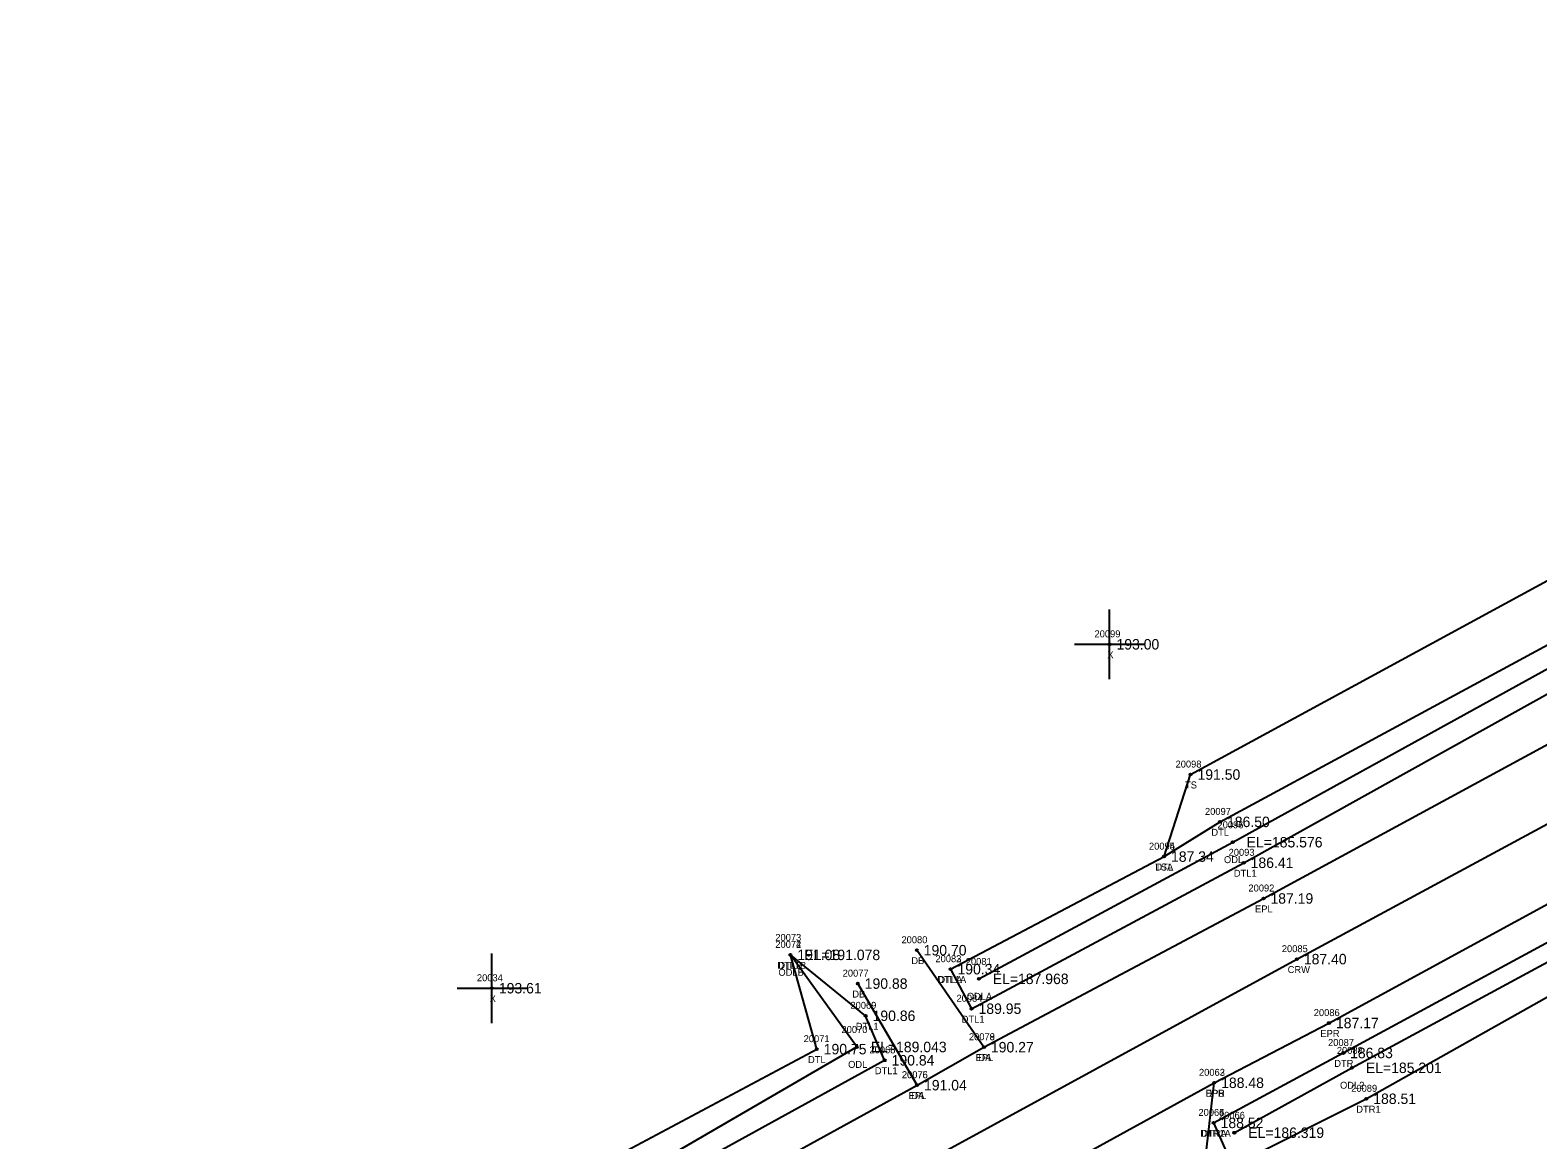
# Model space of a CAD drawing. Extents: x 2279528 to 2280976, y 1061373 to 1062235.
# Drawn here: x 2279546.3 to 2279762.5, y 1061498.9 to 1061658.1 of the extents above; entities that cross this region are included whole.
import ezdxf

# ---------------------------------------------------------------- set-up
doc = ezdxf.new("R2010")
doc.units = 0
for name, color, linetype in [('RD_DTM_BkLn1', 7, 'Continuous'), ('RD_DTM_BkLn2', 7, 'Continuous'), ('RD_DTM_BkLn_txCode', 7, 'Continuous'), ('RD_EX_Driveway', 7, 'Continuous'), ('RD_EX_Driveway_txCode', 7, 'Continuous'), ('RD_EX_H2O', 7, 'Continuous'), ('RD_EX_H2O_txCode', 7, 'Continuous'), ('RD_EX_Misc', 7, 'Continuous'), ('RD_EX_Misc_txCode', 7, 'Continuous'), ('RD_EX_Road', 7, 'Continuous'), ('RD_EX_Road_txCode', 7, 'Continuous'), ('RD_EX_TX_Driveway_ELEV', 7, 'Continuous'), ('RD_EX_TX_H2O_ELEV', 7, 'Continuous'), ('RD_EX_TX_Misc_ELEV', 7, 'Continuous'), ('RD_EX_TX_Road_ELEV', 7, 'Continuous'), ('RD_HC_Survey_ELEV', 7, 'Continuous'), ('RD_HC_Survey_txCode', 7, 'Continuous'), ('RD_SMD_Locator', 7, 'Continuous')]:
    doc.layers.add(name, color=color, linetype=linetype)

msp = doc.modelspace()

# ---------------------------------------------------------------- linework, layer by layer
at = {"layer": 'RD_DTM_BkLn1'}
msp.add_lwpolyline([(2279559.79, 1061433.13), (2279641.23, 1061477.49), (2279727.93, 1061524.84), (2279814.76, 1061571.75), (2279901.26, 1061618.64), (2279982.8, 1061662.56), (2280064.7, 1061706.86), (2280148.08, 1061751.86), (2280234.22, 1061798.46), (2280310.96, 1061840.01), (2280397.69, 1061887.57), (2280487.27, 1061936.5), (2280573.03, 1061983.12), (2280654.64, 1062027.66), (2280741.28, 1062074.45), (2280833.39, 1062123.87), (2280892.52, 1062155.9), (2280939.46, 1062181.85)], dxfattribs=at)
at = {"layer": 'RD_DTM_BkLn2'}
msp.add_lwpolyline([(2279708.88, 1061539.55), (2279712.68, 1061551.32), (2279799.03, 1061598.26), (2279864.37, 1061637.89), (2279890.29, 1061645.53)], dxfattribs=at)
at = {"layer": 'RD_EX_Driveway'}
for p, q in [((2279683.06, 1061512.21), (2279673.42, 1061526.12)), ((2279673.46, 1061506.76), (2279664.96, 1061521.33))]:
    msp.add_line(p, q, dxfattribs=at)
msp.add_lwpolyline([(2279687.22, 1061491.24), (2279694.36, 1061490.16), (2279705.74, 1061483.55), (2279717.08, 1061489.5), (2279714.88, 1061496.65), (2279716.07, 1061507.1)], dxfattribs=at)
at = {"layer": 'RD_EX_H2O'}
for points in [[(2279678.26, 1061523.4), (2279708.88, 1061539.55), (2279716.91, 1061544.53), (2279803.91, 1061591.58), (2279817.92, 1061601.16), (2279890.29, 1061645.53), (2279903.5, 1061647.72), (2279912.54, 1061647.23), (2279918.28, 1061645.97)], [(2279682.32, 1061522.01), (2279718.73, 1061541.61), (2279805.01, 1061589.19), (2279818.85, 1061600.16), (2279890.75, 1061643.58), (2279903.5, 1061647.72)], [(2279678.26, 1061523.4), (2279681.28, 1061517.73), (2279720.3, 1061538.66), (2279806.21, 1061586.46), (2279822.44, 1061595.21), (2279894.25, 1061633.83), (2279918.28, 1061645.97)], [(2279715.99, 1061501.35), (2279734.56, 1061511.38), (2279821.65, 1061558.53), (2279857.43, 1061578.68), (2279860, 1061573.39)], [(2279718.96, 1061499.94), (2279735.82, 1061509.25), (2279822.86, 1061556.33), (2279855.49, 1061575.73)], [(2279715.99, 1061501.35), (2279718.69, 1061495.17), (2279737.88, 1061504.81), (2279824.53, 1061553.58), (2279860, 1061573.39)], [(2279546.29, 1061453.71), (2279630.41, 1061496.6), (2279659.08, 1061511.93), (2279655.3, 1061525.45)], [(2279549.3, 1061448.96), (2279632.68, 1061493.55), (2279664.83, 1061512.24), (2279655.3, 1061525.45)], [(2279552, 1061445.3), (2279634.13, 1061491.29), (2279668.82, 1061510.33), (2279666.09, 1061516.71), (2279655.3, 1061525.45)]]:
    msp.add_lwpolyline(points, dxfattribs=at)
at = {"layer": 'RD_EX_Misc'}
for p, q in [((2279701.06, 1061565), (2279701.06, 1061575)), ((2279696.06, 1061570), (2279706.06, 1061570)), ((2279612.5, 1061515.67), (2279612.5, 1061525.67)), ((2279607.5, 1061520.67), (2279617.5, 1061520.67))]:
    msp.add_line(p, q, dxfattribs=at)
at = {"layer": 'RD_EX_Road'}
for points in [[(2279554.31, 1061441.46), (2279636.61, 1061486.51), (2279673.46, 1061506.76), (2279683.06, 1061512.21), (2279723.14, 1061533.54), (2279809.28, 1061580.29), (2279896.91, 1061627.91), (2279977.07, 1061671.02), (2280059.64, 1061715.57), (2280142.91, 1061760.72), (2280228.83, 1061807.06), (2280306.04, 1061849.18), (2280392.98, 1061896.71), (2280482.82, 1061945.75), (2280567.83, 1061991.78), (2280649.94, 1062036.55), (2280660.56, 1062042.19), (2280676.12, 1062050.66), (2280737.28, 1062083.64), (2280828.54, 1062132.77), (2280887.86, 1062164.61), (2280934.91, 1062190.9)], [(2279563.73, 1061423.75), (2279645.81, 1061468.43), (2279687.22, 1061491.24), (2279716.07, 1061507.1), (2279732.53, 1061515.67), (2279819.45, 1061563.03), (2279856.79, 1061583.22), (2279872.52, 1061591.57), (2279906, 1061609.76), (2279987.33, 1061653.65)]]:
    msp.add_lwpolyline(points, dxfattribs=at)
at = {"layer": 'RD_SMD_Locator'}
for centre in [(2279701.06, 1061570), (2279712.68, 1061551.32), (2279716.91, 1061544.53), (2279718.73, 1061541.61), (2279708.88, 1061539.55), (2279708.88, 1061539.55), (2279720.3, 1061538.66), (2279723.14, 1061533.54), (2279655.3, 1061525.45), (2279655.3, 1061525.45), (2279655.3, 1061525.45), (2279673.42, 1061526.12), (2279727.93, 1061524.84), (2279678.26, 1061523.4), (2279678.26, 1061523.4), (2279612.5, 1061520.67), (2279664.96, 1061521.33), (2279682.32, 1061522.01), (2279681.28, 1061517.73), (2279666.09, 1061516.71), (2279732.53, 1061515.67), (2279659.08, 1061511.93), (2279664.83, 1061512.24), (2279683.06, 1061512.21), (2279683.06, 1061512.21), (2279734.56, 1061511.38), (2279668.82, 1061510.33), (2279735.82, 1061509.25), (2279716.07, 1061507.1), (2279716.07, 1061507.1), (2279673.46, 1061506.76), (2279673.46, 1061506.76), (2279737.88, 1061504.81), (2279715.99, 1061501.35), (2279715.99, 1061501.35), (2279718.96, 1061499.94)]:
    msp.add_circle(centre, 0.15, dxfattribs=at)

# ---------------------------------------------------------------- texts
at = {"layer": 'RD_DTM_BkLn_txCode'}
for s, p in [('20098', (2279710.53, 1061552.32)), ('TS', (2279711.89, 1061549.32)), ('20095', (2279706.72, 1061540.55)), ('TSA', (2279707.6, 1061537.55))]:
    msp.add_text(s, height=1, dxfattribs=at).set_placement(p)
at = {"layer": 'RD_EX_Driveway_txCode'}
for s, p in [('20080', (2279671.23, 1061527.12)), ('DB', (2279672.64, 1061524.12)), ('20077', (2279662.8, 1061522.33)), ('DB', (2279664.18, 1061519.33)), ('20078', (2279680.9, 1061513.21)), ('DA', (2279682.27, 1061510.21)), ('20076', (2279671.28, 1061507.76)), ('20062', (2279713.89, 1061508.1)), ('DA', (2279672.66, 1061504.76)), ('DPB', (2279714.82, 1061505.1))]:
    msp.add_text(s, height=1, dxfattribs=at).set_placement(p)
at = {"layer": 'RD_EX_H2O_txCode'}
for s, p in [('20097', (2279714.75, 1061545.53)), ('20096', (2279716.55, 1061543.61)), ('DTL', (2279715.67, 1061542.53)), ('20094', (2279706.72, 1061540.55)), ('ODL', (2279717.48, 1061538.61)), ('20093', (2279718.14, 1061539.66)), ('DTL', (2279707.64, 1061537.55)), ('DTL1', (2279718.89, 1061536.66)), ('20073', (2279653.14, 1061527.45)), ('20072', (2279653.14, 1061526.45)), ('20074', (2279653.14, 1061526.45)), ('DTL1B', (2279653.42, 1061523.45)), ('DTLB', (2279653.58, 1061523.45)), ('20082', (2279676.1, 1061524.4)), ('20083', (2279676.1, 1061524.4)), ('20081', (2279680.45, 1061524.01)), ('ODLB', (2279653.58, 1061522.45)), ('DTL1A', (2279676.36, 1061521.4)), ('DTLA', (2279676.53, 1061521.4)), ('20069', (2279663.91, 1061517.71)), ('20084', (2279679.12, 1061518.73)), ('ODLA', (2279680.59, 1061519.01)), ('DTL1', (2279664.68, 1061514.71)), ('DTL1', (2279679.87, 1061515.73)), ('20071', (2279657.2, 1061512.93)), ('20070', (2279662.63, 1061514.24)), ('20068', (2279666.64, 1061511.33)), ('20087', (2279732.4, 1061512.38)), ('20088', (2279733.66, 1061511.25)), ('DTL', (2279657.83, 1061509.93)), ('ODL', (2279663.58, 1061509.24)), ('DTL1', (2279667.41, 1061508.33)), ('DTR', (2279733.29, 1061509.38)), ('ODL2', (2279734.12, 1061506.25)), ('20089', (2279735.72, 1061505.81)), ('20064', (2279713.81, 1061502.35)), ('20065', (2279713.81, 1061502.35)), ('20066', (2279716.76, 1061501.94)), ('DTR1', (2279736.45, 1061502.81)), ('DTR1A', (2279714.07, 1061499.35)), ('DTRA', (2279714.23, 1061499.35))]:
    msp.add_text(s, height=1, dxfattribs=at).set_placement(p)
at = {"layer": 'RD_EX_Misc_txCode'}
for s, p in [('20099', (2279698.91, 1061571)), ('X', (2279700.75, 1061568)), ('20034', (2279610.35, 1061521.67)), ('X', (2279612.19, 1061518.67))]:
    msp.add_text(s, height=1, dxfattribs=at).set_placement(p)
at = {"layer": 'RD_EX_Road_txCode'}
for s, p in [('20092', (2279720.98, 1061534.54)), ('EPL', (2279721.93, 1061531.54)), ('20086', (2279730.35, 1061516.67)), ('20079', (2279680.9, 1061513.21)), ('EPR', (2279731.3, 1061513.67)), ('EPL', (2279681.86, 1061510.21)), ('20075', (2279671.3, 1061507.76)), ('20063', (2279713.89, 1061508.1)), ('EPL', (2279672.25, 1061504.76)), ('EPR', (2279714.84, 1061505.1))]:
    msp.add_text(s, height=1, dxfattribs=at).set_placement(p)
at = {"layer": 'RD_EX_TX_Driveway_ELEV'}
for s, p in [('190.70', (2279674.42, 1061525.37)), ('190.88', (2279665.96, 1061520.58)), ('190.27', (2279684.06, 1061511.46)), ('191.04', (2279674.46, 1061506.01)), ('188.48', (2279717.07, 1061506.35))]:
    msp.add_text(s, height=1.5, dxfattribs=at).set_placement(p)
at = {"layer": 'RD_EX_TX_H2O_ELEV'}
for s, p in [('186.50', (2279717.91, 1061543.78)), ('EL=185.576', (2279720.73, 1061540.86)), ('187.34', (2279709.88, 1061538.8)), ('186.41', (2279721.3, 1061537.91)), ('191.08', (2279656.3, 1061524.7)), ('191.08', (2279656.3, 1061524.7)), ('EL=191.078', (2279657.3, 1061524.7)), ('190.34', (2279679.26, 1061522.65)), ('190.34', (2279679.26, 1061522.65)), ('EL=187.968', (2279684.32, 1061521.26)), ('189.95', (2279682.28, 1061516.98)), ('190.86', (2279667.09, 1061515.96)), ('190.75', (2279660.08, 1061511.18)), ('EL=189.043', (2279666.83, 1061511.49)), ('186.83', (2279735.56, 1061510.63)), ('190.84', (2279669.82, 1061509.58)), ('EL=185.201', (2279737.82, 1061508.5)), ('188.51', (2279738.88, 1061504.06)), ('188.52', (2279716.99, 1061500.6)), ('188.52', (2279716.99, 1061500.6)), ('EL=186.319', (2279720.96, 1061499.19))]:
    msp.add_text(s, height=1.5, dxfattribs=at).set_placement(p)
at = {"layer": 'RD_EX_TX_Misc_ELEV'}
for s, p in [('193.00', (2279702.06, 1061569.25)), ('191.50', (2279713.68, 1061550.57)), ('187.34', (2279709.88, 1061538.8)), ('193.61', (2279613.5, 1061519.92))]:
    msp.add_text(s, height=1.5, dxfattribs=at).set_placement(p)
at = {"layer": 'RD_EX_TX_Road_ELEV'}
for s, p in [('187.19', (2279724.14, 1061532.79)), ('187.17', (2279733.53, 1061514.92)), ('190.27', (2279684.06, 1061511.46)), ('191.04', (2279674.46, 1061506.01)), ('188.48', (2279717.07, 1061506.35))]:
    msp.add_text(s, height=1.5, dxfattribs=at).set_placement(p)
at = {"layer": 'RD_HC_Survey_ELEV'}
msp.add_text('187.40', height=1.5, dxfattribs=at).set_placement((2279728.93, 1061524.09))
at = {"layer": 'RD_HC_Survey_txCode'}
for s, p in [('20085', (2279725.77, 1061525.84)), ('CRW', (2279726.61, 1061522.84))]:
    msp.add_text(s, height=1, dxfattribs=at).set_placement(p)

doc.saveas('drawing.dxf')
